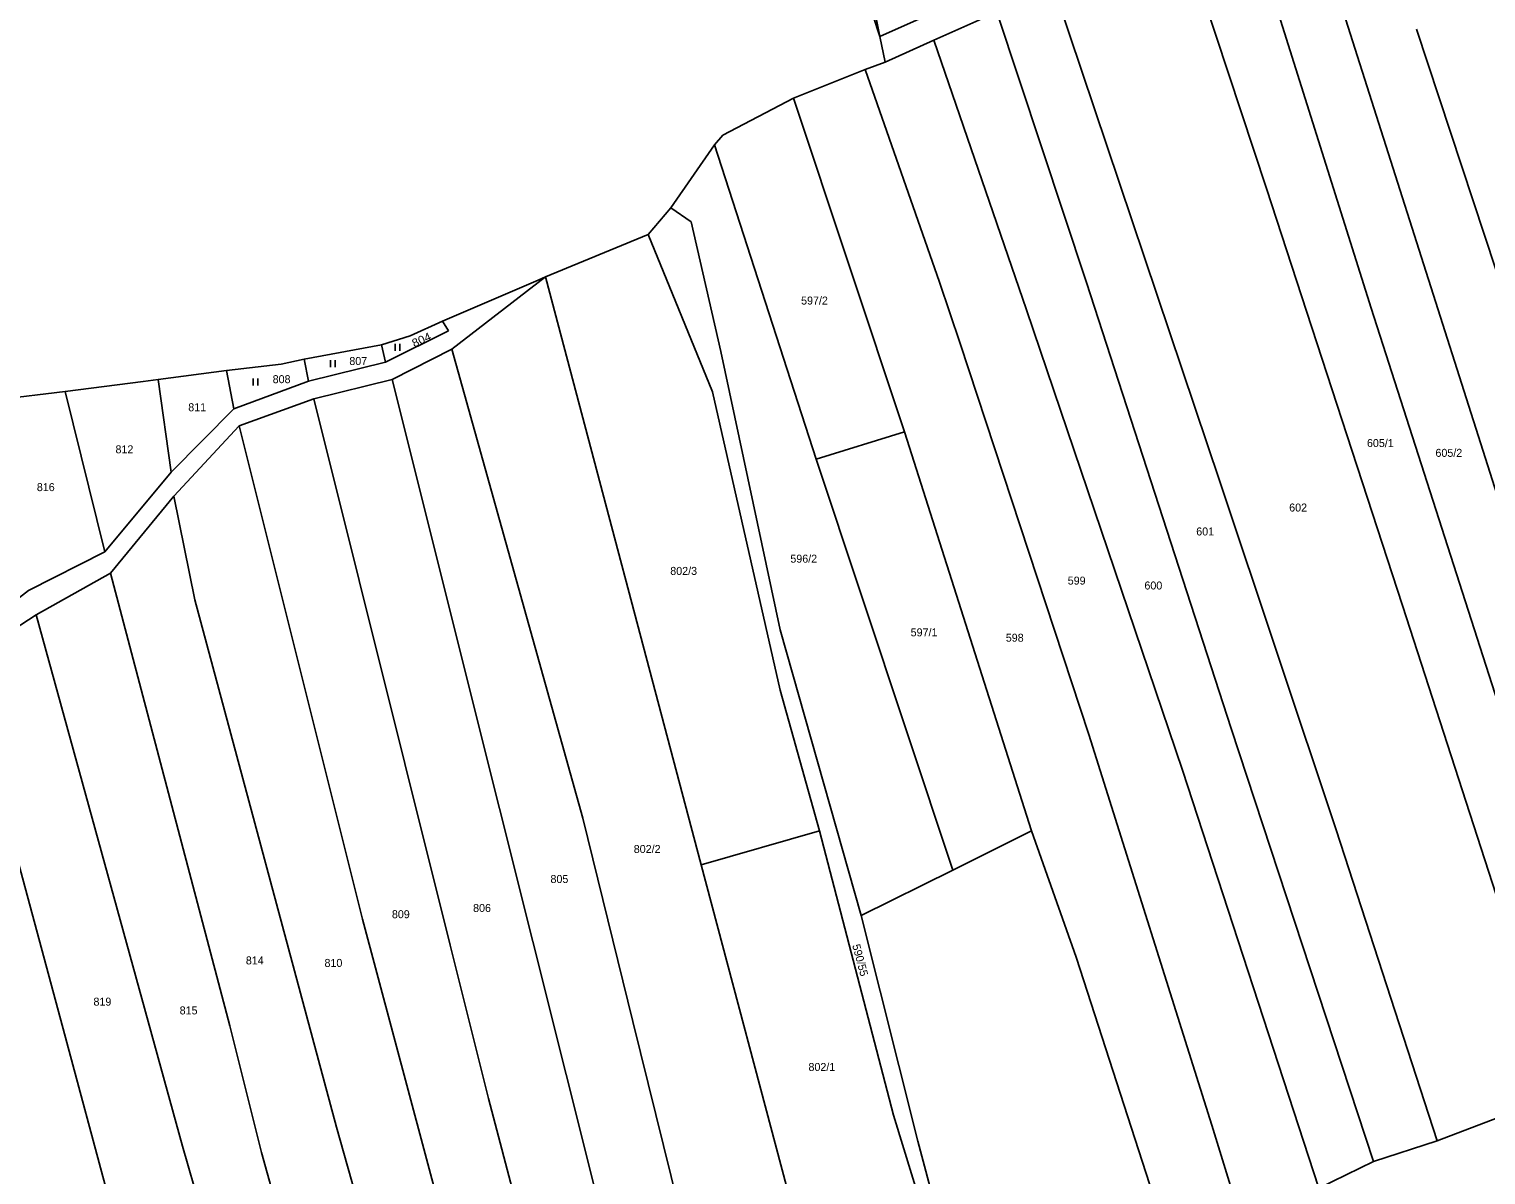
# Model space of a CAD drawing. Extents: x -820420 to -815896, y -1105820 to -1103643.
# Drawn here: x -817682.2 to -817372.7, y -1104314.4 to -1104071 of the extents above; entities that cross this region are included whole.
import ezdxf
from ezdxf.enums import TextEntityAlignment as Align

# ---------------------------------------------------------------- set-up
doc = ezdxf.new("R2010")
doc.units = 0
doc.header["$LTSCALE"] = 0.68
doc.layers.add('1', color=7, linetype='Continuous', lineweight=25)
doc.layers.add('3', color=7, linetype='Continuous', lineweight=25)
doc.layers.add('2', color=7, linetype='Continuous')

msp = doc.modelspace()

# ---------------------------------------------------------------- linework, layer by layer
at = {"layer": '1'}
for p, q in [((-817510, -1104030.09), (-817501.48, -1104072.53)), ((-817362.91, -1104193.32), (-817412.4, -1104037.76)), ((-817424.61, -1104042.84), (-817397.07, -1104130.28)), ((-817501.48, -1104072.53), (-817437.65, -1104043.89)), ((-817419.32, -1104104.86), (-817437.86, -1104048.53)), ((-817501.48, -1104072.53), (-817506.04, -1104058.6)), ((-817465.02, -1104060.6), (-817429.23, -1104167.1)), ((-817476.62, -1104067.36), (-817489.95, -1104073.37)), ((-817457.57, -1104124.86), (-817476.62, -1104067.36)), ((-817346.76, -1104194.45), (-817387.43, -1104070.99)), ((-817500.29, -1104077.99), (-817501.48, -1104072.53)), ((-817489.95, -1104073.37), (-817500.29, -1104077.99)), ((-817489.95, -1104073.37), (-817470.33, -1104130.62)), ((-817519.82, -1104085.64), (-817504.6, -1104079.61)), ((-817500.29, -1104077.99), (-817504.6, -1104079.61)), ((-817504.6, -1104079.61), (-817488.75, -1104124.75)), ((-817534.8, -1104093.5), (-817519.82, -1104085.64)), ((-817496.19, -1104156.55), (-817519.82, -1104085.64)), ((-817545.83, -1104108.93), (-817536.58, -1104095.59)), ((-817536.58, -1104095.59), (-817534.8, -1104093.5)), ((-817536.58, -1104095.59), (-817514.95, -1104162.34)), ((-817390.44, -1104193.44), (-817419.32, -1104104.86)), ((-817545.83, -1104108.93), (-817550.7, -1104114.63)), ((-817541.57, -1104111.96), (-817545.83, -1104108.93)), ((-817535.25, -1104139.51), (-817541.57, -1104111.96)), ((-817572.48, -1104123.65), (-817550.7, -1104114.63)), ((-817550.7, -1104114.63), (-817537.03, -1104148.08)), ((-817572.48, -1104123.65), (-817592.37, -1104138.97)), ((-817572.48, -1104123.65), (-817574.01, -1104124.31)), ((-817539.42, -1104248.56), (-817572.48, -1104123.65)), ((-817574.01, -1104124.31), (-817594.36, -1104133.07)), ((-817488.75, -1104124.75), (-817484.42, -1104137.81)), ((-817426.78, -1104219.54), (-817457.57, -1104124.86)), ((-817470.33, -1104130.62), (-817437.15, -1104228.43)), ((-817397.07, -1104130.28), (-817367.02, -1104223.76)), ((-817606.5, -1104141.78), (-817593.12, -1104135.11)), ((-817601.22, -1104136.18), (-817594.36, -1104133.07)), ((-817593.12, -1104135.11), (-817594.36, -1104133.07)), ((-817623.77, -1104141.08), (-817607.34, -1104138.06)), ((-817607.34, -1104138.06), (-817601.22, -1104136.18)), ((-817606.5, -1104141.78), (-817607.34, -1104138.06)), ((-817592.37, -1104138.97), (-817605.06, -1104145.44)), ((-817592.37, -1104138.97), (-817564.56, -1104238.64)), ((-817484.42, -1104137.81), (-817457.04, -1104220.86)), ((-817640.28, -1104143.54), (-817628.62, -1104142.17)), ((-817628.62, -1104142.17), (-817623.77, -1104141.08)), ((-817622.82, -1104145.79), (-817623.77, -1104141.08)), ((-817622.82, -1104145.79), (-817606.5, -1104141.78)), ((-817522.61, -1104198.6), (-817535.25, -1104139.51)), ((-817654.78, -1104145.42), (-817640.28, -1104143.54)), ((-817640.28, -1104143.54), (-817638.71, -1104151.63)), ((-817674.56, -1104147.95), (-817688.72, -1104149.65)), ((-817657.97, -1104145.83), (-817674.56, -1104147.95)), ((-817674.56, -1104147.95), (-817666.12, -1104182.06)), ((-817654.78, -1104145.42), (-817657.97, -1104145.83)), ((-817652.04, -1104165.15), (-817654.78, -1104145.42)), ((-817638.71, -1104151.63), (-817622.82, -1104145.79)), ((-817605.06, -1104145.44), (-817621.71, -1104149.52)), ((-817582.28, -1104236.55), (-817605.06, -1104145.44)), ((-817537.03, -1104148.08), (-817522.6, -1104211.41)), ((-817621.71, -1104149.52), (-817637.59, -1104155.24)), ((-817621.71, -1104149.52), (-817592.77, -1104265.59)), ((-817638.71, -1104151.63), (-817652.04, -1104165.15)), ((-817637.59, -1104155.24), (-817651.41, -1104170.21)), ((-817611.37, -1104260.07), (-817637.59, -1104155.24)), ((-817496.19, -1104156.55), (-817514.95, -1104162.34)), ((-817469.24, -1104241.32), (-817496.19, -1104156.55)), ((-817514.95, -1104162.34), (-817485.95, -1104249.68)), ((-817666.12, -1104182.06), (-817652.04, -1104165.15)), ((-817429.23, -1104167.1), (-817404.51, -1104241.08)), ((-817651.41, -1104170.21), (-817664.9, -1104186.57)), ((-817651.41, -1104170.21), (-817647.01, -1104192.27)), ((-817664.9, -1104186.57), (-817680.7, -1104195.45)), ((-817639.57, -1104282.72), (-817664.9, -1104186.57)), ((-817647.01, -1104192.27), (-817616.87, -1104304.26)), ((-817356.88, -1104297.14), (-817390.44, -1104193.44)), ((-817680.7, -1104195.45), (-817696, -1104205.37)), ((-817680.7, -1104195.45), (-817649.61, -1104308.28)), ((-817505.4, -1104259.32), (-817522.61, -1104198.6)), ((-817675.46, -1104281.51), (-817696, -1104205.37)), ((-817522.6, -1104211.41), (-817514.24, -1104241.33)), ((-817396.58, -1104311.54), (-817426.78, -1104219.54)), ((-817457.04, -1104220.86), (-817430.92, -1104303.86)), ((-817437.15, -1104228.43), (-817408.2, -1104317.26)), ((-817553.47, -1104351.25), (-817582.28, -1104236.55)), ((-817564.56, -1104238.64), (-817553.93, -1104281.84)), ((-817404.51, -1104241.08), (-817383.05, -1104307.17)), ((-817514.24, -1104241.33), (-817539.42, -1104248.56)), ((-817514.24, -1104241.33), (-817498.55, -1104301.71)), ((-817485.95, -1104249.68), (-817469.24, -1104241.32)), ((-817459.72, -1104268.13), (-817469.24, -1104241.32)), ((-817514.55, -1104342.23), (-817539.42, -1104248.56)), ((-817485.95, -1104249.68), (-817505.4, -1104259.32)), ((-817493.38, -1104307.27), (-817505.4, -1104259.32)), ((-817585.02, -1104358.71), (-817611.37, -1104260.07)), ((-817592.77, -1104265.59), (-817584.6, -1104298.18)), ((-817440.21, -1104328.44), (-817459.72, -1104268.13)), ((-817651.64, -1104370.06), (-817675.46, -1104281.51)), ((-817632.79, -1104309.65), (-817639.57, -1104282.72)), ((-817553.93, -1104281.84), (-817537.59, -1104347.95)), ((-817569.58, -1104355.02), (-817584.6, -1104298.18)), ((-817383.05, -1104307.17), (-817356.88, -1104297.14)), ((-817498.55, -1104301.71), (-817487.95, -1104336.37)), ((-817616.87, -1104304.26), (-817600.7, -1104361.82)), ((-817430.92, -1104303.86), (-817424.97, -1104323.17)), ((-817649.61, -1104308.28), (-817632.6, -1104367.19)), ((-817486.49, -1104332.81), (-817493.38, -1104307.27)), ((-817396.58, -1104311.54), (-817383.05, -1104307.17)), ((-817617.61, -1104364.89), (-817632.79, -1104309.65)), ((-817408.2, -1104317.26), (-817396.58, -1104311.54))]:
    msp.add_line(p, q, dxfattribs=at)
msp.add_lwpolyline([(-817696.51, -1104201.22), (-817682.32, -1104190.25), (-817666.12, -1104182.06)], dxfattribs=at)
at = {"layer": '3'}
for p, q in [((-817604.431, -1104139.35), (-817604.431, -1104137.85)), ((-817603.43, -1104139.35), (-817603.43, -1104137.85)), ((-817618.151, -1104142.84), (-817618.151, -1104141.34)), ((-817617.15, -1104142.84), (-817617.15, -1104141.34)), ((-817634.591, -1104146.7), (-817634.591, -1104145.2)), ((-817633.59, -1104146.7), (-817633.59, -1104145.2))]:
    msp.add_line(p, q, dxfattribs=at)

# ---------------------------------------------------------------- texts
at = {"layer": '2'}
for s, p in [('597/2', (-817515.34, -1104129.515)), ('807', (-817612.259, -1104142.355)), ('808', (-817628.549, -1104146.215)), ('811', (-817646.479, -1104152.175)), ('812', (-817661.939, -1104161.115)), ('605/1', (-817395.12, -1104159.785)), ('605/2', (-817380.57, -1104161.865)), ('816', (-817678.649, -1104169.145)), ('602', (-817412.589, -1104173.485)), ('601', (-817432.339, -1104178.565)), ('802/3', (-817543.13, -1104186.945)), ('596/2', (-817517.62, -1104184.345)), ('599', (-817459.639, -1104189.005)), ('600', (-817443.349, -1104190.045)), ('597/1', (-817492.06, -1104199.995)), ('598', (-817472.799, -1104201.135)), ('802/2', (-817550.89, -1104246.025)), ('805', (-817569.529, -1104252.395)), ('809', (-817603.219, -1104259.875)), ('806', (-817585.969, -1104258.555)), ('814', (-817634.249, -1104269.695)), ('810', (-817617.539, -1104270.225)), ('819', (-817666.619, -1104278.455)), ('815', (-817648.309, -1104280.315)), ('802/1', (-817513.77, -1104292.325))]:
    msp.add_text(s, height=1.7, dxfattribs=at).set_placement(p, align=Align.CENTER)
at = {"layer": '2', "width": 1.1}
msp.add_text('804', height=1.7, rotation=24, dxfattribs=at).set_placement((-817598.4907, -1104137.7596), align=Align.CENTER)
at = {"layer": '2'}
msp.add_text('590/55', height=1.7, rotation=285, dxfattribs=at).set_placement((-817506.4399, -1104269.001), align=Align.CENTER)

doc.saveas('drawing.dxf')
